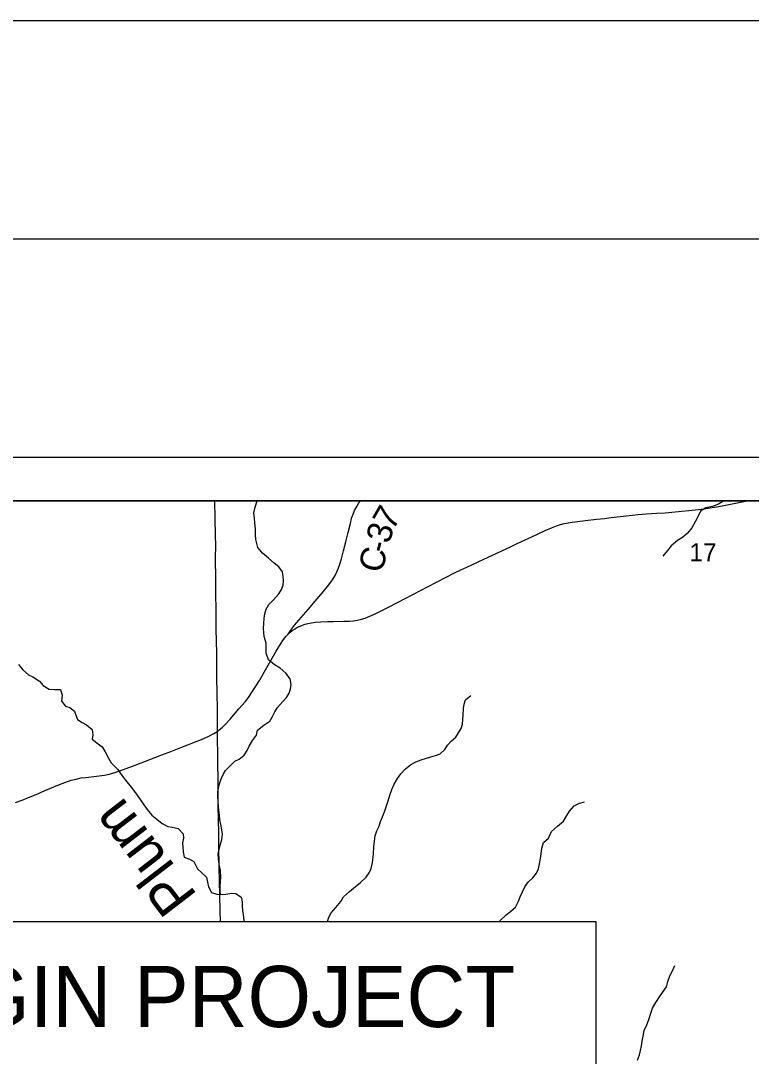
# Model space of a CAD drawing. Extents: x -7.5 to 53.5, y 0 to 22.
# Drawn here: x 4.57 to 6.245, y 19.628 to 22 of the extents above; entities that cross this region are included whole.
import ezdxf

# ---------------------------------------------------------------- set-up
doc = ezdxf.new("R2010")
doc.units = 0
for name, color, linetype in [('GM_X_Corporation', 7, 'Continuous'), ('GM_X_County_Road', 7, 'Continuous'), ('GM_X_County_Road_Text', 7, 'Continuous'), ('GM_X_Minor_River', 7, 'Continuous'), ('GM_X_Minor_River_Text', 7, 'Continuous'), ('GM_X_Section_Text', 7, 'Continuous'), ('GM_X_Township_Road', 7, 'Continuous'), ('SH_Border', 7, 'Continuous'), ('SH_Cut_Line', 7, 'Continuous'), ('SH_Data', 7, 'Continuous'), ('SH_Text', 7, 'Continuous')]:
    doc.layers.add(name, color=color, linetype=linetype)

msp = doc.modelspace()

# ---------------------------------------------------------------- linework, layer by layer
at = {"layer": 'GM_X_Corporation'}
msp.add_lwpolyline([(4.6087, 14.5302), (4.6021, 15.6139), (4.594, 15.8096), (4.5873, 16.3533), (4.5872, 16.3635), (4.5826, 16.8462), (4.5822, 16.8992), (4.577, 17.1178), (4.5749, 17.2575), (4.5771, 17.6201), (4.5718, 18.1276), (4.5696, 18.2604), (4.5565, 19.1354), (5.0411, 19.1401), (6.0424, 19.1527), (6.0433, 19.1527), (6.5522, 19.1561), (7.544, 19.1455), (8.414, 19.1709), (8.5159, 19.1718), (8.9, 19.1887), (8.9, 20.9), (2.1, 20.9), (2.1, 14.1)], dxfattribs=at)
at = {"layer": 'GM_X_County_Road'}
for points in [[(5.1828, 20.5948), (5.1893, 20.6039), (5.1935, 20.6097), (5.1976, 20.615), (5.2027, 20.6211), (5.2075, 20.6271), (5.2126, 20.6328), (5.2289, 20.6515), (5.2452, 20.6703), (5.2635, 20.6915), (5.2734, 20.7035), (5.2808, 20.7135), (5.2861, 20.7213), (5.2908, 20.7294), (5.2948, 20.7378), (5.2983, 20.7465), (5.3013, 20.7553), (5.305, 20.7673), (5.3099, 20.7853), (5.3154, 20.8062), (5.3205, 20.8273), (5.3255, 20.8483), (5.3285, 20.8601), (5.3317, 20.8697), (5.3352, 20.878), (5.3396, 20.8856), (5.3453, 20.8953), (5.3487, 20.9)], [(5.1828, 20.5948), (5.1878, 20.5994), (5.1925, 20.603), (5.1978, 20.6065), (5.2047, 20.6104), (5.2108, 20.6133), (5.216, 20.6152), (5.2218, 20.6173), (5.2277, 20.619), (5.2367, 20.6209), (5.2459, 20.6221), (5.2582, 20.6231), (5.2737, 20.6237), (5.2861, 20.6239), (5.3109, 20.6242), (5.3233, 20.6247), (5.3325, 20.6256), (5.3418, 20.6269), (5.3509, 20.6289), (5.3594, 20.6313), (5.3704, 20.6358), (5.3827, 20.6412), (5.4127, 20.6564), (5.4334, 20.6673), (5.5038, 20.7042), (5.5451, 20.7255), (5.5645, 20.7353), (5.5785, 20.7418), (5.5926, 20.7483), (5.6319, 20.7668), (5.6601, 20.7797), (5.6742, 20.7861), (5.6911, 20.7942), (5.705, 20.8008), (5.7191, 20.8074), (5.7332, 20.8139), (5.7528, 20.8232), (5.7725, 20.8325), (5.7867, 20.8386), (5.7983, 20.8431), (5.8071, 20.846), (5.816, 20.8482), (5.8251, 20.85), (5.8342, 20.8514), (5.8649, 20.8552), (5.8895, 20.8581), (5.9079, 20.86), (5.9233, 20.8619), (5.9851, 20.8687), (6.0036, 20.8704), (6.0284, 20.8718), (6.047, 20.873), (6.0779, 20.8755), (6.1088, 20.8786), (6.1366, 20.882), (6.155, 20.8848), (6.1703, 20.8875), (6.2008, 20.8936), (6.2313, 20.8994), (6.2342, 20.9)], [(5.0209, 20.3725), (5.0278, 20.3777), (5.0325, 20.3818), (5.0392, 20.3884), (5.0497, 20.3998), (5.0701, 20.4233), (5.0841, 20.44), (5.0917, 20.4498), (5.1007, 20.4625), (5.1092, 20.4755), (5.1173, 20.4888), (5.1281, 20.5077), (5.1434, 20.5347), (5.1553, 20.5559), (5.1655, 20.572), (5.1723, 20.5825), (5.1781, 20.59), (5.1828, 20.5948)], [(4.5582, 20.2092), (4.5733, 20.2147), (4.5879, 20.2202), (4.6057, 20.2274), (4.624, 20.2354), (4.6585, 20.2501), (4.6709, 20.255), (4.6859, 20.2601), (4.697, 20.2628), (4.7088, 20.2654), (4.7195, 20.2667), (4.7495, 20.2703), (4.762, 20.272), (4.7724, 20.2742), (4.7814, 20.2766), (4.7903, 20.2794), (4.8056, 20.2849), (4.8324, 20.2949), (4.8934, 20.3179), (4.9138, 20.3256), (4.9296, 20.3317), (4.9411, 20.3362), (4.9527, 20.3408), (4.9642, 20.3454), (4.9843, 20.3537), (5.0013, 20.3613), (5.0123, 20.3671), (5.0203, 20.372), (5.0209, 20.3725)], [(5.0276, 19.9368), (5.0273, 19.9602), (5.0262, 19.9975), (5.0255, 20.0285), (5.0251, 20.0596), (5.0242, 20.1124), (5.0238, 20.1404), (5.0233, 20.1683), (5.0229, 20.2025), (5.0224, 20.2615), (5.0221, 20.2988), (5.0216, 20.3298), (5.0213, 20.3453), (5.0209, 20.3725)]]:
    msp.add_lwpolyline(points, dxfattribs=at)
at = {"layer": 'GM_X_Minor_River'}
for points in [[(5.028, 19.9982), (5.0273, 20.0076), (5.0273, 20.0182), (5.0276, 20.0277), (5.0283, 20.0379), (5.0279, 20.0531), (5.0248, 20.0672), (5.0232, 20.0797), (5.0228, 20.0907), (5.0243, 20.1002), (5.0269, 20.1112), (5.031, 20.1241), (5.0325, 20.1355), (5.0313, 20.1465), (5.0286, 20.1586), (5.0266, 20.1696), (5.0255, 20.1799), (5.0235, 20.1981), (5.0223, 20.211), (5.0215, 20.2227), (5.0214, 20.2337), (5.0252, 20.2497), (5.0289, 20.2607), (5.0338, 20.2729), (5.0391, 20.2824), (5.0519, 20.2942), (5.0606, 20.3037), (5.0704, 20.3083), (5.0825, 20.3178), (5.0893, 20.3281), (5.0934, 20.3384), (5.1013, 20.3513), (5.1103, 20.3631), (5.1126, 20.3749), (5.1269, 20.3859), (5.1409, 20.3951), (5.1469, 20.4061), (5.1522, 20.4164), (5.1582, 20.427), (5.171, 20.4404), (5.179, 20.4499), (5.185, 20.4594), (5.1887, 20.4697), (5.1898, 20.4792), (5.1875, 20.4924), (5.178, 20.5053), (5.1643, 20.5166), (5.1517, 20.5242), (5.1377, 20.5359), (5.1327, 20.551), (5.1322, 20.562), (5.1326, 20.5738), (5.1283, 20.5894), (5.1264, 20.6079), (5.1271, 20.6193), (5.1278, 20.6311), (5.1293, 20.641), (5.1326, 20.652), (5.139, 20.6626), (5.1485, 20.6729), (5.1617, 20.687), (5.1677, 20.6969), (5.1718, 20.7072), (5.1725, 20.7174), (5.1717, 20.7269), (5.1698, 20.7371), (5.1614, 20.7489), (5.1511, 20.7576), (5.1378, 20.7689), (5.1241, 20.7806), (5.1135, 20.7935), (5.1092, 20.8113), (5.1084, 20.8212), (5.1084, 20.836), (5.1068, 20.85), (5.1056, 20.8595), (5.1044, 20.8724), (5.107, 20.8857), (5.1121, 20.9)], [(6.1829, 20.9), (6.1795, 20.8984), (6.1697, 20.8927), (6.1557, 20.8873), (6.1405, 20.8839), (6.1284, 20.8762), (6.1232, 20.8648), (6.1164, 20.8534), (6.1081, 20.8386), (6.0983, 20.826), (6.0866, 20.8165), (6.0753, 20.8089), (6.0613, 20.7967), (6.0526, 20.7864), (6.0421, 20.7731)], [(4.5651, 20.5254), (4.5746, 20.5129), (4.5875, 20.5012), (4.5974, 20.497), (4.6126, 20.4872), (4.6214, 20.4774), (4.6354, 20.4683), (4.6475, 20.4676), (4.6612, 20.468), (4.665, 20.4548), (4.6636, 20.4415), (4.6723, 20.4298), (4.6826, 20.4268), (4.6929, 20.4184), (4.6963, 20.409), (4.6998, 20.3995), (4.7108, 20.392), (4.7207, 20.3871), (4.7336, 20.3761), (4.7355, 20.3643), (4.7337, 20.3545), (4.7443, 20.3454), (4.7565, 20.3363), (4.7634, 20.3254), (4.7714, 20.3106), (4.7771, 20.3), (4.7923, 20.2849), (4.8, 20.2731), (4.8099, 20.2603), (4.8232, 20.2444), (4.8327, 20.2315), (4.8419, 20.2183), (4.8522, 20.2039), (4.8594, 20.1933), (4.8705, 20.1804), (4.8819, 20.171), (4.8944, 20.1612), (4.9069, 20.1544), (4.9168, 20.1525), (4.9305, 20.1495)], [(5.2732, 19.9368), (5.2732, 19.9368), (5.2762, 19.9463), (5.2815, 19.9562), (5.2924, 19.9687), (5.3037, 19.9821), (5.3101, 19.9927), (5.3237, 20.0049), (5.3377, 20.0167), (5.3479, 20.0251), (5.3618, 20.0381), (5.3686, 20.0476), (5.3735, 20.0578), (5.3765, 20.0719), (5.3776, 20.0837), (5.3783, 20.0932), (5.3794, 20.1064), (5.3808, 20.1205), (5.3827, 20.133), (5.386, 20.144), (5.3913, 20.1551), (5.395, 20.1657), (5.3992, 20.176), (5.4048, 20.19), (5.4081, 20.2014), (5.4123, 20.2132), (5.416, 20.2257), (5.4209, 20.239), (5.4261, 20.2512), (5.4333, 20.2638), (5.4416, 20.2748), (5.4518, 20.2858), (5.4635, 20.295), (5.4756, 20.3019), (5.4877, 20.3065), (5.4975, 20.3095), (5.5104, 20.3134), (5.521, 20.3165), (5.5312, 20.3203), (5.5418, 20.3302), (5.5482, 20.3401), (5.5572, 20.35), (5.567, 20.3584), (5.5734, 20.3683), (5.5795, 20.3789), (5.5824, 20.3888), (5.5835, 20.3994), (5.5843, 20.4093), (5.585, 20.4245), (5.5864, 20.4347), (5.5894, 20.4442), (5.6019, 20.4538)], [(5.6671, 19.9368), (5.6685, 19.9383), (5.6824, 19.9516), (5.6923, 19.9592), (5.7043, 19.9695), (5.7111, 19.9828), (5.7152, 19.9931), (5.7201, 20.0041), (5.7258, 20.0155), (5.7333, 20.0266), (5.7435, 20.0361), (5.7525, 20.0475), (5.7567, 20.0574), (5.7593, 20.0684), (5.7611, 20.0806), (5.7626, 20.0912), (5.7644, 20.1041), (5.7682, 20.1174), (5.7799, 20.1277), (5.7866, 20.1425), (5.8002, 20.1551), (5.8138, 20.1661), (5.8221, 20.1795), (5.8277, 20.1893), (5.8387, 20.2015), (5.8508, 20.2073), (5.8621, 20.2107)], [(4.9305, 20.1495), (4.9423, 20.1371), (4.9434, 20.1276), (4.9408, 20.1166), (4.9413, 20.1067), (4.9421, 20.0957), (4.9448, 20.0836), (4.9565, 20.0794), (4.9664, 20.0738), (4.9748, 20.0571), (4.9851, 20.0477), (4.9957, 20.0378), (4.9981, 20.0268), (5.0004, 20.0162), (5.0073, 20.003), (5.0194, 19.9992), (5.0293, 19.9981), (5.0402, 19.9993), (5.0535, 20.0012), (5.063, 20.0005), (5.0755, 19.9922), (5.0775, 19.9812), (5.0779, 19.9717), (5.0783, 19.9619), (5.0795, 19.952), (5.081, 19.9402), (5.082, 19.9368)], [(5.9836, 19.6188), (5.9881, 19.6313), (5.9903, 19.6408), (5.9933, 19.6515), (5.9948, 19.6621), (5.9966, 19.6739), (5.9992, 19.6864), (6.0049, 19.7001), (6.0097, 19.7123), (6.0142, 19.7263), (6.018, 19.7377), (6.0255, 19.751), (6.036, 19.7659), (6.0504, 19.7864), (6.0537, 19.7993), (6.0578, 19.8122), (6.0639, 19.8236), (6.0695, 19.8358)]]:
    msp.add_lwpolyline(points, dxfattribs=at)
at = {"layer": 'GM_X_Township_Road'}
msp.add_lwpolyline([(5.0209, 20.3725), (5.0207, 20.3822), (5.0208, 20.3935), (5.0207, 20.4204), (5.0202, 20.4616), (5.0197, 20.4934), (5.0193, 20.518), (5.0195, 20.534), (5.0191, 20.5462), (5.0184, 20.5836), (5.0181, 20.6018), (5.0181, 20.6269), (5.018, 20.6517), (5.0175, 20.6858), (5.0171, 20.723), (5.0167, 20.7663), (5.0168, 20.8004), (5.0166, 20.819), (5.0157, 20.8624), (5.0151, 20.8965), (5.0151, 20.9)], dxfattribs=at)
at = {"layer": 'SH_Border'}
msp.add_lwpolyline([(1.5, 21.5), (33.5, 21.5), (33.5, 0.5), (1.5, 0.5)], close=True, dxfattribs=at)
at = {"layer": 'SH_Cut_Line'}
msp.add_lwpolyline([(0, 0), (34, 0), (34, 22), (0, 22)], close=True, dxfattribs=at)
at = {"layer": 'SH_Data'}
for p, q in [((2, 21), (9, 21)), ((2.1, 20.9), (8.9, 20.9))]:
    msp.add_line(p, q, dxfattribs=at)
at = {"layer": 'SH_Text'}
msp.add_lwpolyline([(4.0742, 19.9368), (5.8885, 19.9368), (5.8885, 19.3693), (4.0742, 19.3693)], close=True, dxfattribs=at)

# ---------------------------------------------------------------- texts
at = {"layer": 'GM_X_County_Road_Text'}
for s, rotation, p in [('7', 60.168, (5.4229, 20.8302)), ('3', 74.8681, (5.4152, 20.8)), ('C', 75.587, (5.3978, 20.7324)), ('-', 75.5151, (5.4094, 20.7775))]:
    msp.add_text(s, height=0.0568, rotation=rotation, dxfattribs=at).set_placement(p)
at = {"layer": 'GM_X_Minor_River_Text'}
msp.add_text('Plum', height=0.09472, rotation=127.4935, dxfattribs=at).set_placement((4.9767, 19.996))
at = {"layer": 'GM_X_Section_Text'}
msp.add_text('17', height=0.04186, rotation=0, dxfattribs=at).set_placement((6.1028, 20.7612))
at = {"layer": 'SH_Text'}
msp.add_text('BEGIN PROJECT', height=0.14, dxfattribs=at).set_placement((4.1953, 19.6947))

doc.saveas('drawing.dxf')
